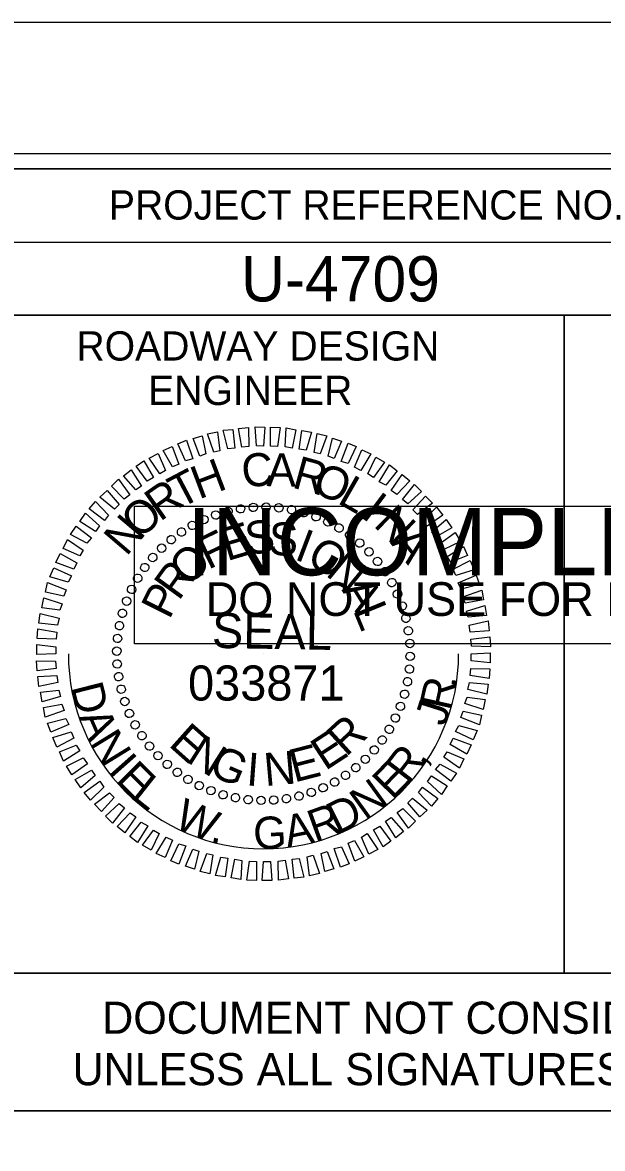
# Model space of a CAD drawing. Extents: x 1779926 to 1781610, y 602514 to 621564.
# Drawn here: x 1781400.4 to 1781499.5, y 603422 to 603614.5 of the extents above; entities that cross this region are included whole.
import ezdxf

# ---------------------------------------------------------------- set-up
doc = ezdxf.new("R2010")
doc.units = 0
for name, color, linetype in [('Old_Level_58', 7, 'Continuous'), ('Scratch_Level_0', 7, 'Continuous'), ('Sheet Data Field CELL', 7, 'Continuous'), ('Sheet Plot Border Inside CELL', 7, 'Continuous'), ('Sheet Plot Border Outside CELL', 7, 'Continuous'), ('Sheet Professional Seal CELL', 7, 'Continuous'), ('Sheet Profile CELL', 7, 'Continuous'), ('Sheet Profile Grid Major CELL', 7, 'Continuous'), ('Sheet Profile Grid Minor CELL', 7, 'Continuous'), ('Sheet Sticker Exception Certification CELL', 7, 'Continuous'), ('Sheet Sticker Incomplete CELL', 7, 'Continuous')]:
    doc.layers.add(name, color=color, linetype=linetype)

msp = doc.modelspace()

# ---------------------------------------------------------------- linework, layer by layer
at = {"layer": 'Old_Level_58'}
msp.add_lwpolyline([(1781392.96, 603428.4), (1781592.95, 603428.4), (1781592.95, 603364.45), (1781392.96, 603364.45)], close=True, dxfattribs=at)
at = {"layer": 'Scratch_Level_0'}
msp.add_arc((1781441.55, 603506.54), 33.36, 180, 360, dxfattribs=at)
at = {"layer": 'Sheet Plot Border Inside CELL'}
msp.add_lwpolyline([(1779938.96, 602536.9), (1781605.46, 602536.9), (1781605.46, 603592), (1779938.96, 603592)], close=True, dxfattribs=at)
at = {"layer": 'Sheet Plot Border Outside CELL'}
msp.add_lwpolyline([(1779925.96, 602514.45), (1781609.96, 602514.45), (1781609.96, 603614.45), (1779925.96, 603614.45)], close=True, dxfattribs=at)
at = {"layer": 'Sheet Professional Seal CELL'}
for p, q in [((1781433.35, 603530.29), (1781433.35, 603530.29)), ((1781435.45, 603530.89), (1781435.45, 603530.89)), ((1781437.65, 603531.29), (1781437.65, 603531.29)), ((1781439.8, 603531.59), (1781439.8, 603531.59)), ((1781442, 603531.64), (1781442, 603531.64)), ((1781444.2, 603531.49), (1781444.2, 603531.49)), ((1781446.35, 603531.14), (1781446.35, 603531.14)), ((1781448.45, 603530.69), (1781448.45, 603530.69)), ((1781450.55, 603529.99), (1781450.55, 603529.99)), ((1781429.4, 603528.49), (1781429.4, 603528.49)), ((1781431.35, 603529.49), (1781431.35, 603529.49)), ((1781452.55, 603529.09), (1781452.55, 603529.09)), ((1781454.5, 603528.09), (1781454.5, 603528.09)), ((1781425.75, 603526.09), (1781425.75, 603526.09)), ((1781427.5, 603527.34), (1781427.5, 603527.34)), ((1781456.3, 603526.84), (1781456.3, 603526.84)), ((1781424.1, 603524.59), (1781424.1, 603524.59)), ((1781458.05, 603525.49), (1781458.05, 603525.49)), ((1781422.6, 603523.04), (1781422.6, 603523.04)), ((1781459.6, 603523.99), (1781459.6, 603523.99)), ((1781461.1, 603522.34), (1781461.1, 603522.34)), ((1781421.25, 603521.29), (1781421.25, 603521.29)), ((1781462.35, 603520.59), (1781462.35, 603520.59)), ((1781420, 603519.49), (1781420, 603519.49)), ((1781463.5, 603518.69), (1781463.5, 603518.69)), ((1781419, 603517.54), (1781419, 603517.54)), ((1781464.5, 603516.74), (1781464.5, 603516.74)), ((1781418.1, 603515.54), (1781418.1, 603515.54)), ((1781465.3, 603514.74), (1781465.3, 603514.74)), ((1781417.4, 603513.44), (1781417.4, 603513.44)), ((1781465.9, 603512.64), (1781465.9, 603512.64)), ((1781416.95, 603511.34), (1781416.95, 603511.34)), ((1781416.6, 603509.19), (1781416.6, 603509.19)), ((1781466.3, 603510.44), (1781466.3, 603510.44)), ((1781416.45, 603506.99), (1781416.45, 603506.99)), ((1781466.6, 603508.29), (1781466.6, 603508.29)), ((1781441.55, 603506.54), (1781441.55, 603506.54)), ((1781466.65, 603506.09), (1781466.65, 603506.09)), ((1781416.5, 603504.79), (1781416.5, 603504.79)), ((1781466.5, 603503.89), (1781466.5, 603503.89)), ((1781416.8, 603502.64), (1781416.8, 603502.64)), ((1781466.15, 603501.74), (1781466.15, 603501.74)), ((1781417.2, 603500.44), (1781417.2, 603500.44)), ((1781465.7, 603499.64), (1781465.7, 603499.64)), ((1781417.8, 603498.34), (1781417.8, 603498.34)), ((1781465, 603497.54), (1781465, 603497.54)), ((1781418.6, 603496.34), (1781418.6, 603496.34)), ((1781464.1, 603495.54), (1781464.1, 603495.54)), ((1781419.6, 603494.39), (1781419.6, 603494.39)), ((1781463.1, 603493.59), (1781463.1, 603493.59)), ((1781420.75, 603492.49), (1781420.75, 603492.49)), ((1781461.85, 603491.79), (1781461.85, 603491.79)), ((1781422, 603490.74), (1781422, 603490.74)), ((1781460.5, 603490.04), (1781460.5, 603490.04)), ((1781423.5, 603489.09), (1781423.5, 603489.09)), ((1781425.05, 603487.59), (1781425.05, 603487.59)), ((1781459, 603488.49), (1781459, 603488.49)), ((1781426.8, 603486.24), (1781426.8, 603486.24)), ((1781455.6, 603485.74), (1781455.6, 603485.74)), ((1781457.35, 603486.99), (1781457.35, 603486.99)), ((1781428.6, 603484.99), (1781428.6, 603484.99)), ((1781430.55, 603483.99), (1781430.55, 603483.99)), ((1781453.7, 603484.59), (1781453.7, 603484.59)), ((1781432.55, 603483.09), (1781432.55, 603483.09)), ((1781434.65, 603482.39), (1781434.65, 603482.39)), ((1781436.75, 603481.94), (1781436.75, 603481.94)), ((1781445.45, 603481.79), (1781445.45, 603481.79)), ((1781447.65, 603482.19), (1781447.65, 603482.19)), ((1781449.75, 603482.79), (1781449.75, 603482.79)), ((1781451.75, 603483.59), (1781451.75, 603483.59)), ((1781438.9, 603481.59), (1781438.9, 603481.59)), ((1781441.1, 603481.44), (1781441.1, 603481.44)), ((1781443.3, 603481.49), (1781443.3, 603481.49))]:
    msp.add_line(p, q, dxfattribs=at)
for points in [[(1781440.35, 603542.09), (1781440.1, 603545.34), (1781441.75, 603545.29), (1781441.55, 603542.04)], [(1781442.75, 603542.04), (1781442.75, 603545.29), (1781444.4, 603545.24), (1781443.95, 603541.99)], [(1781430.65, 603540.34), (1781429.5, 603543.34), (1781431.05, 603543.79), (1781431.7, 603540.69)], [(1781433.05, 603540.99), (1781432, 603544.14), (1781433.7, 603544.49), (1781434.1, 603541.24)], [(1781435.45, 603541.54), (1781434.65, 603544.74), (1781436.3, 603544.89), (1781436.65, 603541.69)], [(1781437.85, 603541.84), (1781437.3, 603545.04), (1781439, 603545.24), (1781439.05, 603541.99)], [(1781445.25, 603541.89), (1781445.45, 603545.14), (1781447.1, 603544.84), (1781446.45, 603541.69)], [(1781447.65, 603541.49), (1781448.1, 603544.69), (1781449.75, 603544.44), (1781448.85, 603541.34)], [(1781450.2, 603540.94), (1781450.7, 603544.19), (1781452.4, 603543.79), (1781451.25, 603540.69)], [(1781452.6, 603540.29), (1781453.35, 603543.39), (1781454.9, 603542.89), (1781453.65, 603539.94)], [(1781426, 603538.49), (1781424.4, 603541.29), (1781425.95, 603541.99), (1781427.1, 603538.94)], [(1781428.2, 603539.54), (1781426.9, 603542.44), (1781428.4, 603543.04), (1781429.45, 603539.84)], [(1781454.85, 603539.39), (1781456, 603542.54), (1781457.4, 603541.94), (1781456, 603539.04)], [(1781421.65, 603536.04), (1781419.8, 603538.59), (1781421.1, 603539.54), (1781422.75, 603536.64)], [(1781423.85, 603537.29), (1781422, 603539.99), (1781423.55, 603540.79), (1781424.8, 603537.89)], [(1781457.1, 603538.44), (1781458.35, 603541.39), (1781459.9, 603540.69), (1781458.2, 603537.89)], [(1781459.4, 603537.29), (1781460.75, 603540.14), (1781462.25, 603539.29), (1781460.35, 603536.69)], [(1781419.75, 603534.54), (1781417.6, 603536.94), (1781418.95, 603537.99), (1781420.7, 603535.19)], [(1781461.35, 603535.94), (1781463.1, 603538.84), (1781464.4, 603537.79), (1781462.45, 603535.34)], [(1781417.75, 603532.99), (1781415.55, 603535.19), (1781416.75, 603536.39), (1781418.7, 603533.69)], [(1781463.4, 603534.44), (1781465.25, 603537.19), (1781466.55, 603536.09), (1781464.35, 603533.74)], [(1781416.1, 603531.24), (1781413.55, 603533.29), (1781414.8, 603534.44), (1781416.9, 603532.04)], [(1781465.3, 603532.89), (1781467.35, 603535.49), (1781468.55, 603534.29), (1781466.25, 603532.14)], [(1781414.35, 603529.34), (1781411.75, 603531.29), (1781412.85, 603532.59), (1781415.05, 603530.24)], [(1781467.1, 603531.14), (1781469.25, 603533.49), (1781470.45, 603532.29), (1781467.85, 603530.34)], [(1781412.85, 603527.44), (1781410.15, 603529.14), (1781411.1, 603530.59), (1781413.5, 603528.39)], [(1781468.85, 603529.34), (1781471.15, 603531.59), (1781472.2, 603530.24), (1781469.55, 603528.34)], [(1781411.35, 603525.44), (1781408.55, 603526.94), (1781409.55, 603528.34), (1781412.15, 603526.34)], [(1781470.35, 603527.39), (1781472.8, 603529.49), (1781473.75, 603528.04), (1781470.95, 603526.44)], [(1781410.15, 603523.29), (1781407.3, 603524.54), (1781408.05, 603526.09), (1781410.75, 603524.24)], [(1781471.65, 603525.34), (1781474.3, 603527.24), (1781475.25, 603525.74), (1781472.35, 603524.34)], [(1781472.95, 603523.14), (1781475.75, 603524.89), (1781476.4, 603523.34), (1781473.55, 603522.19)], [(1781409.15, 603520.99), (1781406.05, 603522.14), (1781406.8, 603523.69), (1781409.65, 603522.09)], [(1781473.95, 603520.99), (1781476.9, 603522.49), (1781477.55, 603520.89), (1781474.45, 603519.89)], [(1781408.15, 603518.79), (1781405.05, 603519.69), (1781405.7, 603521.24), (1781408.7, 603519.84)], [(1781407.4, 603516.39), (1781404.3, 603517.04), (1781404.65, 603518.69), (1781407.8, 603517.44)], [(1781474.85, 603518.64), (1781477.9, 603519.94), (1781478.45, 603518.39), (1781475.35, 603517.59)], [(1781475.65, 603516.24), (1781478.85, 603517.39), (1781479.15, 603515.74), (1781476, 603515.19)], [(1781406.75, 603513.99), (1781403.65, 603514.39), (1781404, 603516.09), (1781407.15, 603515.04)], [(1781476.25, 603513.84), (1781479.4, 603514.79), (1781479.7, 603513.09), (1781476.55, 603512.79)], [(1781406.35, 603511.44), (1781403.15, 603511.74), (1781403.35, 603513.44), (1781406.6, 603512.64)], [(1781406.1, 603509.04), (1781402.85, 603509.14), (1781402.95, 603510.79), (1781406.2, 603510.24)], [(1781476.7, 603511.44), (1781479.95, 603512.14), (1781480.1, 603510.44), (1781476.9, 603510.24)], [(1781477, 603509.04), (1781480.25, 603509.44), (1781480.35, 603507.74), (1781477.1, 603507.84)], [(1781406.05, 603506.54), (1781402.8, 603506.39), (1781402.8, 603508.09), (1781406.05, 603507.74)], [(1781406.1, 603504.04), (1781402.85, 603503.64), (1781402.75, 603505.34), (1781406, 603505.24)], [(1781477.05, 603506.54), (1781480.3, 603506.69), (1781480.3, 603504.99), (1781477.05, 603505.34)], [(1781477, 603504.04), (1781480.25, 603503.94), (1781480.15, 603502.29), (1781476.9, 603502.84)], [(1781406.4, 603501.64), (1781403.15, 603500.94), (1781403, 603502.64), (1781406.2, 603502.84)], [(1781476.75, 603501.64), (1781479.95, 603501.34), (1781479.75, 603499.64), (1781476.5, 603500.44)], [(1781406.85, 603499.24), (1781403.7, 603498.29), (1781403.4, 603499.99), (1781406.55, 603500.29)], [(1781476.35, 603499.09), (1781479.45, 603498.69), (1781479.1, 603496.99), (1781475.95, 603498.04)], [(1781407.45, 603496.84), (1781404.25, 603495.69), (1781403.95, 603497.34), (1781407.1, 603497.89)], [(1781408.25, 603494.44), (1781405.2, 603493.14), (1781404.65, 603494.69), (1781407.75, 603495.49)], [(1781475.7, 603496.69), (1781478.8, 603496.04), (1781478.45, 603494.39), (1781475.3, 603495.64)], [(1781474.95, 603494.29), (1781478.05, 603493.39), (1781477.4, 603491.84), (1781474.4, 603493.24)], [(1781409.15, 603492.09), (1781406.2, 603490.59), (1781405.55, 603492.19), (1781408.65, 603493.19)], [(1781473.95, 603492.09), (1781477.05, 603490.94), (1781476.3, 603489.39), (1781473.45, 603490.99)], [(1781410.15, 603489.94), (1781407.35, 603488.19), (1781406.7, 603489.74), (1781409.55, 603490.89)], [(1781472.95, 603489.79), (1781475.8, 603488.54), (1781475.05, 603486.99), (1781472.35, 603488.84)], [(1781411.45, 603487.74), (1781408.8, 603485.84), (1781407.85, 603487.34), (1781410.75, 603488.74)], [(1781471.75, 603487.64), (1781474.55, 603486.14), (1781473.55, 603484.74), (1781470.95, 603486.74)], [(1781412.75, 603485.69), (1781410.3, 603483.59), (1781409.35, 603485.04), (1781412.15, 603486.64)], [(1781470.25, 603485.64), (1781472.95, 603483.94), (1781472, 603482.49), (1781469.6, 603484.69)], [(1781414.25, 603483.74), (1781411.95, 603481.49), (1781410.9, 603482.84), (1781413.55, 603484.74)], [(1781468.75, 603483.74), (1781471.35, 603481.79), (1781470.25, 603480.49), (1781468.05, 603482.84)], [(1781416, 603481.94), (1781413.85, 603479.59), (1781412.65, 603480.79), (1781415.25, 603482.74)], [(1781467, 603481.84), (1781469.55, 603479.79), (1781468.3, 603478.64), (1781466.2, 603481.04)], [(1781417.8, 603480.19), (1781415.75, 603477.59), (1781414.55, 603478.79), (1781416.85, 603480.94)], [(1781465.35, 603480.09), (1781467.55, 603477.89), (1781466.35, 603476.69), (1781464.4, 603479.39)], [(1781419.7, 603478.64), (1781417.85, 603475.89), (1781416.55, 603476.99), (1781418.75, 603479.34)], [(1781463.35, 603478.54), (1781465.5, 603476.14), (1781464.15, 603475.09), (1781462.4, 603477.89)], [(1781421.75, 603477.14), (1781420, 603474.24), (1781418.7, 603475.29), (1781420.65, 603477.74)], [(1781423.7, 603475.79), (1781422.35, 603472.94), (1781420.85, 603473.79), (1781422.75, 603476.39)], [(1781461.45, 603477.04), (1781463.3, 603474.49), (1781462, 603473.54), (1781460.35, 603476.44)], [(1781426, 603474.64), (1781424.75, 603471.69), (1781423.2, 603472.39), (1781424.9, 603475.19)], [(1781428.25, 603473.69), (1781427.1, 603470.54), (1781425.7, 603471.14), (1781427.1, 603474.04)], [(1781457.1, 603474.59), (1781458.7, 603471.79), (1781457.15, 603471.09), (1781456, 603474.14)], [(1781459.25, 603475.79), (1781461.1, 603473.09), (1781459.55, 603472.29), (1781458.3, 603475.19)], [(1781430.5, 603472.79), (1781429.75, 603469.69), (1781428.2, 603470.19), (1781429.45, 603473.14)], [(1781432.9, 603472.14), (1781432.4, 603468.89), (1781430.7, 603469.29), (1781431.85, 603472.39)], [(1781452.45, 603472.74), (1781453.6, 603469.74), (1781452.05, 603469.29), (1781451.4, 603472.39)], [(1781454.9, 603473.54), (1781456.2, 603470.64), (1781454.7, 603470.04), (1781453.65, 603473.24)], [(1781435.45, 603471.59), (1781435, 603468.39), (1781433.35, 603468.64), (1781434.25, 603471.74)], [(1781437.85, 603471.19), (1781437.65, 603467.94), (1781436, 603468.24), (1781436.65, 603471.39)], [(1781440.35, 603471.04), (1781440.35, 603467.79), (1781438.7, 603467.84), (1781439.15, 603471.09)], [(1781442.75, 603470.99), (1781443, 603467.74), (1781441.35, 603467.79), (1781441.55, 603471.04)], [(1781445.25, 603471.24), (1781445.8, 603468.04), (1781444.1, 603467.84), (1781444.05, 603471.09)], [(1781447.65, 603471.54), (1781448.45, 603468.34), (1781446.8, 603468.19), (1781446.45, 603471.39)], [(1781450.05, 603472.09), (1781451.1, 603468.94), (1781449.4, 603468.59), (1781449, 603471.84)]]:
    msp.add_lwpolyline(points, close=True, dxfattribs=at)
for centre, major_axis in [((1781437.63, 603531.31), (-0.113, 0.711)), ((1781439.8, 603531.55), (-0.05, 0.718)), ((1781441.99, 603531.61), (0.013, 0.72)), ((1781444.17, 603531.48), (0.075, 0.716)), ((1781446.34, 603531.16), (0.137, 0.707)), ((1781431.35, 603529.45), (-0.293, 0.658)), ((1781433.38, 603530.25), (-0.234, 0.681)), ((1781435.48, 603530.87), (-0.174, 0.699)), ((1781448.46, 603530.64), (0.198, 0.692)), ((1781450.54, 603529.95), (0.258, 0.672)), ((1781452.54, 603529.08), (0.316, 0.647)), ((1781427.53, 603527.33), (-0.403, 0.597)), ((1781429.39, 603528.47), (-0.349, 0.63)), ((1781454.47, 603528.03), (0.371, 0.617)), ((1781425.77, 603526.03), (-0.453, 0.56)), ((1781456.29, 603526.83), (0.423, 0.582)), ((1781458, 603525.46), (0.472, 0.543)), ((1781424.13, 603524.58), (-0.5, 0.518)), ((1781459.59, 603523.96), (0.518, 0.5)), ((1781422.62, 603522.99), (-0.543, 0.472)), ((1781461.04, 603522.32), (0.56, 0.453)), ((1781420.05, 603519.45), (-0.617, 0.371)), ((1781421.26, 603521.28), (-0.582, 0.423)), ((1781462.34, 603520.56), (0.597, 0.403)), ((1781419.01, 603517.53), (-0.647, 0.316)), ((1781463.49, 603518.69), (0.63, 0.349)), ((1781464.46, 603516.74), (0.658, 0.293)), ((1781418.14, 603515.52), (-0.672, 0.258)), ((1781465.26, 603514.7), (0.681, 0.234)), ((1781417.44, 603513.45), (-0.692, 0.198)), ((1781465.89, 603512.6), (0.699, 0.174)), ((1781416.93, 603511.32), (-0.707, 0.137)), ((1781466.32, 603510.46), (0.711, 0.113)), ((1781416.61, 603509.16), (-0.716, 0.075)), ((1781466.57, 603508.29), (0.718, 0.05)), ((1781416.47, 603506.97), (-0.72, 0.013)), ((1781466.63, 603506.1), (0.72, -0.013)), ((1781416.53, 603504.79), (-0.718, -0.05)), ((1781416.78, 603502.61), (-0.711, -0.113)), ((1781466.49, 603503.91), (0.716, -0.075)), ((1781417.22, 603500.47), (-0.699, -0.174)), ((1781466.17, 603501.75), (0.707, -0.137)), ((1781417.84, 603498.37), (-0.681, -0.234)), ((1781465.66, 603499.62), (0.692, -0.198)), ((1781418.64, 603496.33), (-0.658, -0.293)), ((1781464.96, 603497.55), (0.672, -0.258)), ((1781464.09, 603495.54), (0.647, -0.316)), ((1781419.61, 603494.38), (-0.63, -0.349)), ((1781420.76, 603492.51), (-0.597, -0.403)), ((1781463.05, 603493.62), (0.617, -0.371)), ((1781422.06, 603490.75), (-0.56, -0.453)), ((1781461.84, 603491.79), (0.582, -0.423)), ((1781423.51, 603489.11), (-0.518, -0.5)), ((1781460.48, 603490.08), (0.543, -0.472)), ((1781425.1, 603487.61), (-0.472, -0.543)), ((1781457.33, 603487.05), (0.453, -0.56)), ((1781458.97, 603488.49), (0.5, -0.518)), ((1781426.81, 603486.25), (-0.423, -0.582)), ((1781428.63, 603485.04), (-0.371, -0.617)), ((1781455.57, 603485.74), (0.403, -0.597)), ((1781430.56, 603483.99), (-0.316, -0.647)), ((1781432.56, 603483.12), (-0.258, -0.672)), ((1781451.75, 603483.62), (0.293, -0.658)), ((1781453.71, 603484.6), (0.349, -0.63)), ((1781434.64, 603482.43), (-0.198, -0.692)), ((1781436.76, 603481.92), (-0.137, -0.707)), ((1781438.93, 603481.59), (-0.075, -0.716)), ((1781441.11, 603481.46), (-0.013, -0.72)), ((1781443.3, 603481.52), (0.05, -0.718)), ((1781445.47, 603481.76), (0.113, -0.711)), ((1781447.62, 603482.2), (0.174, -0.699)), ((1781449.72, 603482.82), (0.234, -0.681))]:
    msp.add_ellipse(centre, major_axis=major_axis, ratio=0.999708, dxfattribs=at)
at = {"layer": 'Sheet Profile CELL'}
for p, q in [((1781392.91, 603576.9), (1781592.96, 603576.9)), ((1781492.96, 603564.4), (1781492.96, 603451.95))]:
    msp.add_line(p, q, dxfattribs=at)
for points in [[(1781592.96, 603589.45), (1780092.96, 603589.45), (1780092.96, 602539.45), (1781592.96, 602539.45)], [(1781392.91, 603589.45), (1781592.96, 603589.45), (1781592.96, 603564.4), (1781392.91, 603564.4)], [(1781392.91, 603564.4), (1781492.96, 603564.4), (1781492.96, 603451.9), (1781392.91, 603451.9)], [(1781492.96, 603564.4), (1781592.96, 603564.4), (1781592.96, 603451.9), (1781492.96, 603451.9)]]:
    msp.add_lwpolyline(points, close=True, dxfattribs=at)
at = {"layer": 'Sheet Profile Grid Major CELL'}
msp.add_lwpolyline([(1781142.96, 603089.45), (1781192.96, 603089.45), (1781192.96, 603589.45), (1781242.96, 603589.45), (1781242.96, 603089.45), (1781292.96, 603089.45), (1781292.96, 603589.45), (1781342.96, 603589.45), (1781342.96, 603089.45), (1781392.96, 603089.45), (1781392.96, 603589.45), (1781419.26, 603589.45)], dxfattribs=at)
at = {"layer": 'Sheet Sticker Exception Certification CELL'}
for p, q in [((1781392.91, 603451.9), (1781592.95, 603451.9)), ((1781392.91, 603451.9), (1781592.95, 603451.9)), ((1781592.95, 603428.4), (1781392.91, 603428.4)), ((1781592.95, 603428.4), (1781392.91, 603428.4))]:
    msp.add_line(p, q, dxfattribs=at)
at = {"layer": 'Sheet Sticker Incomplete CELL'}
msp.add_lwpolyline([(1781419.48, 603508.25), (1781419.48, 603531.75), (1781566.48, 603531.75), (1781566.48, 603508.25)], close=True, dxfattribs=at)

# ---------------------------------------------------------------- texts
at = {"layer": 'Sheet Data Field CELL'}
msp.add_text('U-4709', height=7.75, dxfattribs=at).set_placement((1781437.72, 603566.76))
at = {"layer": 'Sheet Professional Seal CELL'}
for s, height, rotation, p in [('H', 5.64, 20.6195, (1781430.5, 603532.89)), ('C', 5.64, 6.2199, (1781438.1, 603534.89)), ('A', 5.64, 359.0203, (1781442.05, 603535.19)), ('R', 5.64, 344.6211, (1781446.25, 603534.99)), ('T', 5.64, 27.8198, (1781427.25, 603531.24)), ('O', 5.64, 337.4212, (1781449.6, 603534.24)), ('R', 5.64, 35.0205, (1781423.85, 603529.04)), ('L', 5.64, 330.2209, (1781454, 603532.39)), ('I', 5.64, 323.0201, (1781458.05, 603529.99)), ('O', 5.64, 42.2217, (1781420.4, 603525.94)), ('N', 5.64, 315.8189, (1781460.2, 603528.44)), ('N', 5.64, 49.4235, (1781418.1, 603523.04)), ('E', 5.64, 16.6111, (1781435.3, 603522.34)), ('S', 5.64, 7.2556, (1781438.75, 603523.39)), ('S', 5.64, 357.9004, (1781442.35, 603523.44)), ('F', 5.64, 25.967, (1781432.1, 603520.84)), ('I', 5.64, 339.1896, (1781446.65, 603522.74)), ('O', 5.64, 329.8335, (1781448.65, 603522.04)), ('A', 5.64, 308.6172, (1781463.15, 603525.49)), ('O', 5.64, 44.6812, (1781428.8, 603517.89)), ('R', 5.64, 54.0397, (1781427.05, 603515.44)), ('N', 5.64, 320.4766, (1781452, 603520.04)), ('P', 5.64, 63.3989, (1781425.45, 603512.24)), ('A', 5.64, 301.7603, (1781454.85, 603517.44)), ('L', 5.64, 292.4008, (1781456.8, 603513.99)), ('SEAL', 5.998, 359, (1781432.7, 603507.54)), ('R', 5.64, 42.4814, (1781455.65, 603488.79)), ('E', 5.64, 318.2769, (1781425.15, 603490.89)), ('E', 5.64, 33.1241, (1781452.1, 603486.44)), ('N', 5.64, 327.634, (1781428.15, 603488.19)), ('G', 5.64, 336.9902, (1781431.95, 603485.94)), ('I', 5.64, 355.7012, (1781438.5, 603484.04)), ('N', 5.64, 5.0564, (1781441.85, 603483.89)), ('E', 5.64, 14.4118, (1781446.8, 603484.49))]:
    msp.add_text(s, height=height, rotation=rotation, dxfattribs=at).set_placement(p)
at = {"layer": 'Sheet Profile CELL'}
for s, height, p in [('PROJECT REFERENCE NO.', 5.0001, (1781415.12, 603580.76)), ('ROADWAY DESIGN', 5.0001, (1781409.57, 603556.66)), ('ENGINEER', 5, (1781421.82, 603549.06))]:
    msp.add_text(s, height=height, dxfattribs=at).set_placement(p)
at = {"layer": 'Sheet Profile Grid Minor CELL'}
msp.add_text('033871', height=5.998, dxfattribs=at).set_placement((1781428.65, 603498.53))
for s, rotation, p in [('D', 284.2682, (1781408.56, 603500.89)), ('R', 77.3541, (1781473.52, 603496.63)), ('.', 84.2805, (1781474.48, 603500.56)), ('J', 72.4855, (1781472.57, 603493.96)), ('A', 293.4128, (1781409.88, 603495.72)), ('N', 301.5986, (1781411.74, 603491.32)), ('I', 311.5304, (1781414.81, 603486.41)), ('R', 52.3788, (1781466.35, 603484.06)), ('E', 315.0508, (1781416.09, 603484.8)), ('E', 45.7958, (1781463.61, 603481.37)), (',', 59.3052, (1781468.88, 603487.22)), ('L', 321.6338, (1781418.75, 603482.03)), ('N', 35.8641, (1781458.94, 603477.94)), ('W', 336.8891, (1781426.01, 603476.89)), ('D', 26.7195, (1781454.17, 603475.54)), ('R', 19.793, (1781450.34, 603474.24)), ('G', 1.6755, (1781439.86, 603473.11)), ('A', 11.6072, (1781445.65, 603473.32)), ('.', 348.4952, (1781432.29, 603474.37))]:
    msp.add_text(s, height=5.5, rotation=rotation, dxfattribs=at).set_placement(p)
at = {"layer": 'Sheet Sticker Exception Certification CELL'}
for s, p in [('DOCUMENT NOT CONSIDERED FINAL', (1781413.98, 603441.56)), ('DOCUMENT NOT CONSIDERED FINAL', (1781413.98, 603441.56)), ('UNLESS ALL SIGNATURES COMPLETED', (1781408.91, 603432.76)), ('UNLESS ALL SIGNATURES COMPLETED', (1781408.91, 603432.76))]:
    msp.add_text(s, height=5.5, dxfattribs=at).set_placement(p)
at = {"layer": 'Sheet Sticker Incomplete CELL'}
for s, height, p in [('INCOMPLETE PLANS', 11.52, (1781428.43, 603519.95)), ('DO NOT USE FOR R/W ACQUISITION', 5.76, (1781431.68, 603513))]:
    msp.add_text(s, height=height, dxfattribs=at).set_placement(p)

doc.saveas('drawing.dxf')
